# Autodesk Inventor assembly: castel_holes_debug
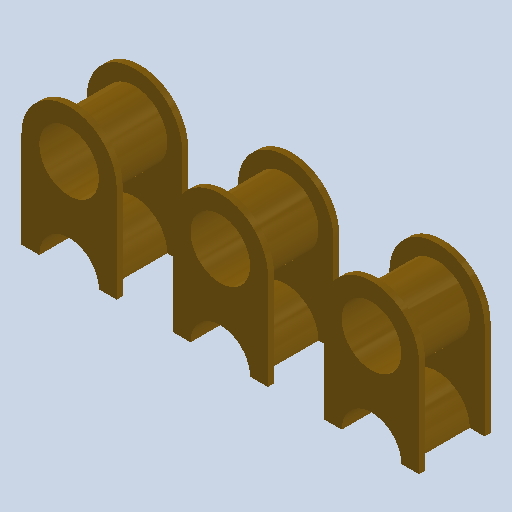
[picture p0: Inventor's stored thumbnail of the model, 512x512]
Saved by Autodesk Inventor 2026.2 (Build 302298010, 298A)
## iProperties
Created: 2026-10
Part Number: castel_holes_debug
Document SubType Name: Assembly
Designer: mel
Author: mel
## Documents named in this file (2)
- D:\travail\année 2026-2027\1 sti2d IT\poubelle à verre\raspberry-pico-2-microcontroller-rp2350-1.snapshot.5\raspberry_pico_2\raspberry_pico_2\castel_holes_debug.iam
- D:\travail\année 2026-2027\1 sti2d IT\poubelle à verre\raspberry-pico-2-microcontroller-rp2350-1.snapshot.5\raspberry_pico_2\raspberry_pico_2\castel_hole001.ipt
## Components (3 placed, 3 different names)
1. 2621
2. 2622
3. 2623
